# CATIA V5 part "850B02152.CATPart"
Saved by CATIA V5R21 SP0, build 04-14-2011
Part number: 850B02152
Bounding box of the stored display mesh (mm): x -3.4 to 3.4, y -74.75 to 74.75, z -82.5 to 82.5
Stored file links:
  C:\Users\ALI OZGUN\Desktop\alhan\TESLIMEDILEN3\850B02152.CATPart
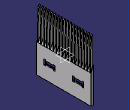
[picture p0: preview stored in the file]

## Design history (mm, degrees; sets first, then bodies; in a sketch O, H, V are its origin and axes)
Body1 (main body)
  Sketch1 on yz-plane, origin (0, 0, 0), H (0, 1, 0), V (0, 0, 1)
    line L1 (-74.75, 12.5) -> (74.75, 12.5)
    line L2 (74.75, 12.5) -> (74.75, -82.5)
    line L3 (74.75, -82.5) -> (-74.75, -82.5)
    line L4 (-74.75, -82.5) -> (-74.75, 12.5)
    length L1 = 149.5
    length L2 = 95
    distance L2 V = 74.75
    distance L3 H = 82.5
    horizontal: L1 H, L3 H
    vertical: L2 V, L4 V
  Pad1: profile Sketch1, direction (1, 0, 0), length 3.4, mirrored extent
  Draft1: Angle 68, Neutral start face of Pad1, PullDir start face of Pad1, SupportToDraft face of Pad1 from Sketch1.L1
  Sketch2 on end face of Pad1, origin (3.4, 0, 0), H (0, 1, 0), V (0, 0, 1)
    line L1 (-54.75, -35) -> (-50, -35)
    line L2 (-23.95, -35) -> (-23.95, -49)
    line L3 (-23.95, -49) -> (-28.7, -49)
    line L4 (-54.75, -49) -> (-54.75, -35)
    line L5 (-50, -35) -> (-50, -37.175)
    line L6 (-50, -37.175) -> (-28.7, -37.175)
    line L7 (-28.7, -37.175) -> (-28.7, -35)
    line L8 (-50, -49) -> (-50, -46.825)
    line L9 (-50, -46.825) -> (-28.7, -46.825)
    point P8 (-28.7, -46.825)
    line L10 (-28.7, -46.825) -> (-28.7, -49)
    point P10 (-28.7, -35)
    line L11 (-28.7, -35) -> (-23.95, -35)
    line L12 (-50, -49) -> (-54.75, -49)
    reference projected line E1 (-74.75, 12.5) -> (-74.75, -82.5) from edge [face of Pad1 from Sketch1.L4 | end face of Pad1]
    reference projected line E2 (-74.75, -82.5) -> (74.75, -82.5) from edge [face of Pad1 from Sketch1.L3 | end face of Pad1]
    distance L4 E1 = 20
    distance L2 L4 = 30.8
    distance L11 L3 = 14
    distance L6 L9 = 9.65
    distance L9 L3 = 2.175
    distance L7 L2 = 4.75
    length L6 = 21.3
    distance L12 E2 = 33.5
    horizontal: L1 H, L3 H, L6 H, L9 H, L11 H, L12 H
    vertical: L2 V, L4 V, L5 V, L7 V, L8 V, L10 V
    coincidence: P8 L7, L1 P10, L1 L11, L3 L12, L8 L5
  Pocket1: profile Sketch2, direction (-1, 0, 0), length 11.4, mirrored extent
  Mirror1: of Pocket1, Sketch2, about zx-plane
  Sketch3 on start face of Pad1, origin (-3.4, 0, 0), H (0, -1, 0), V (0, 0, 1)
    point P2 (23.95, -35)
    point P3 (23.95, -49)
    point P5 (54.75, -35)
    point P6 (54.75, -49)
    point P7 (23.95, -49)
    point P8 (23.95, -35)
    point P9 (54.75, -49)
    point P10 (54.75, -35)
    construction line L1 (28.7, -35) -> (23.95, -35)
    construction line L2 (54.75, -35) -> (23.95, -35)
    construction line L3 (54.75, -35) -> (54.75, -49)
    line L4 (54.75, -35.45) -> (54.75, -48.55)
    construction line L5 (23.95, -49) -> (28.7, -49)
    construction line L6 (23.95, -49) -> (54.75, -49)
    line L7 (23.95, -48.55) -> (23.95, -35.45)
    line L8 (54.75, -35.45) -> (23.95, -35.45)
    line L9 (23.95, -48.55) -> (54.75, -48.55)
    point P11 (23.95, -48.55)
    point P12 (54.75, -48.55)
    construction line L10 (23.95, -49) -> (23.95, -48.55)
    construction line L11 (54.75, -49) -> (54.75, -48.55)
    distance L6 L9 = 0.45
    distance L8 L9 = 13.1
    coincidence: P2 P8, P3 P7, P12 L9, P9 L4, P11 L9, P7 L7, P8 L7, P10 L4
    perpendicularity: L10 L6, L10 L9, L11 L6, L11 L9
    fix: P5, P10, P6, P9, P7, P3, P8, P2, L7, L6, L4, L2
  Pocket2: profile Sketch3, direction (1, 0, 0), length 1.37
  Mirror2: of Pocket2, Sketch3, about zx-plane
  Thickness1: Face (end face of Pocket2; end face of Pocket2; face of Mirror2; face of Mirror2), Thickness -3
  Sketch4 on start face of Pad1, origin (-3.4, 0, 0), H (0, -1, 0), V (0, 0, 1)
    line L1 (23.95, -35) -> (54.75, -35)
    line L2 (54.75, -35) -> (54.75, -49)
    line L3 (54.75, -49) -> (23.95, -49)
    line L4 (23.95, -49) -> (23.95, -35)
    reference projected line E1 (54.75, -49) -> (54.75, -35) from edge [start face of Pad1 | face of Pocket2]
    reference projected line E2 (50, -49) -> (54.75, -49) from edge [start face of Pad1 | face of Pocket1 from Sketch2.L12]
    reference projected line E3 (23.95, -35) -> (23.95, -49) from edge [start face of Pad1 | face of Pocket2]
    reference projected line E4 (54.75, -35) -> (50, -35) from edge [start face of Pad1 | face of Pocket1 from Sketch2.L1]
    horizontal: L1 H, L3 H
    vertical: L2 V, L4 V
    coincidence: L2 E1, L3 E2, L4 E3, L1 E4
  Pocket3: profile Sketch4, direction (1, 0, 0), length 1.37
  Mirror3: of Pocket3, Sketch4, about zx-plane
  Sketch5 on start face of Pad1, origin (-3.4, 0, 0), H (0, -1, 0), V (0, 0, 1)
    line L1 (53.35, -32.3703) -> (65.9384, -32.3703)
    line L2 (65.9384, -32.3703) -> (65.9384, -51.8809)
    line L3 (65.9384, -51.8809) -> (53.35, -51.8809)
    line L4 (53.35, -51.8809) -> (53.35, -32.3703)
    line L5 (18.5519, -30.2393) -> (25.35, -30.2393)
    line L6 (25.35, -30.2393) -> (25.35, -54.0139)
    line L7 (25.35, -54.0139) -> (18.5519, -54.0139)
    line L8 (18.5519, -54.0139) -> (18.5519, -30.2393)
    reference projected line E1 (23.95, -35) -> (23.95, -49) from edge [start face of Pad1 | face of Pocket3]
    distance L4 L6 = 28
    distance L6 E1 = 1.4
    horizontal: L1 H, L3 H, L5 H, L7 H
    vertical: L2 V, L4 V, L6 V, L8 V
  Pad2: profile Sketch5, direction (1, 0, 0), length 3.8
  Mirror4: of Pad2, Sketch5, about zx-plane
  Chamfer1: length 2, second length 3, on edge [face of Pad2 from Sketch5.L6 | face of Mirror4]; edge [face of Pad2 from Sketch5.L4 | face of Mirror4]; edge [face of Mirror4 | face of Mirror4] (x2)
  Body2
    Sketch6 on face of Mirror4, origin (-3.4, 0, 0), H (0, -1, 0), V (0, 0, 1)
      line L1 (-71.89, 82.5) -> (-71.89, -5)
      point P1 (-71.89, 82.5)
      reference projected line E1 (-74.75, -82.5) -> (-74.75, 12.5) from edge [face of Mirror4 | face of Pad1 from Sketch1.L2]
      reference projected line E2 (74.75, -82.5) -> (-74.75, -82.5) from edge [start face of Pad1 | face of Pad1 from Sketch1.L3]
      distance L1 E1 = 2.86
      distance P1 E2 = 165
      length L1 = 87.5
      vertical: L1 V
    Pad3: profile Sketch6, direction (1, 0, 0), length 6.543, thin wall 2.72
    Chamfer2: length 40, second length 3, on edge [end face of Pad3 | face of Pad3]
    Chamfer3: length 2, second length 2, on edge [face of Chamfer2 | face of Pad3]
    RectPattern1: of the body so far, direction 1 instances 18, spacing 8.44, along edge [face of Pad1 from Sketch1.L1 | end face of Pad1]
  Add1: tool Body2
